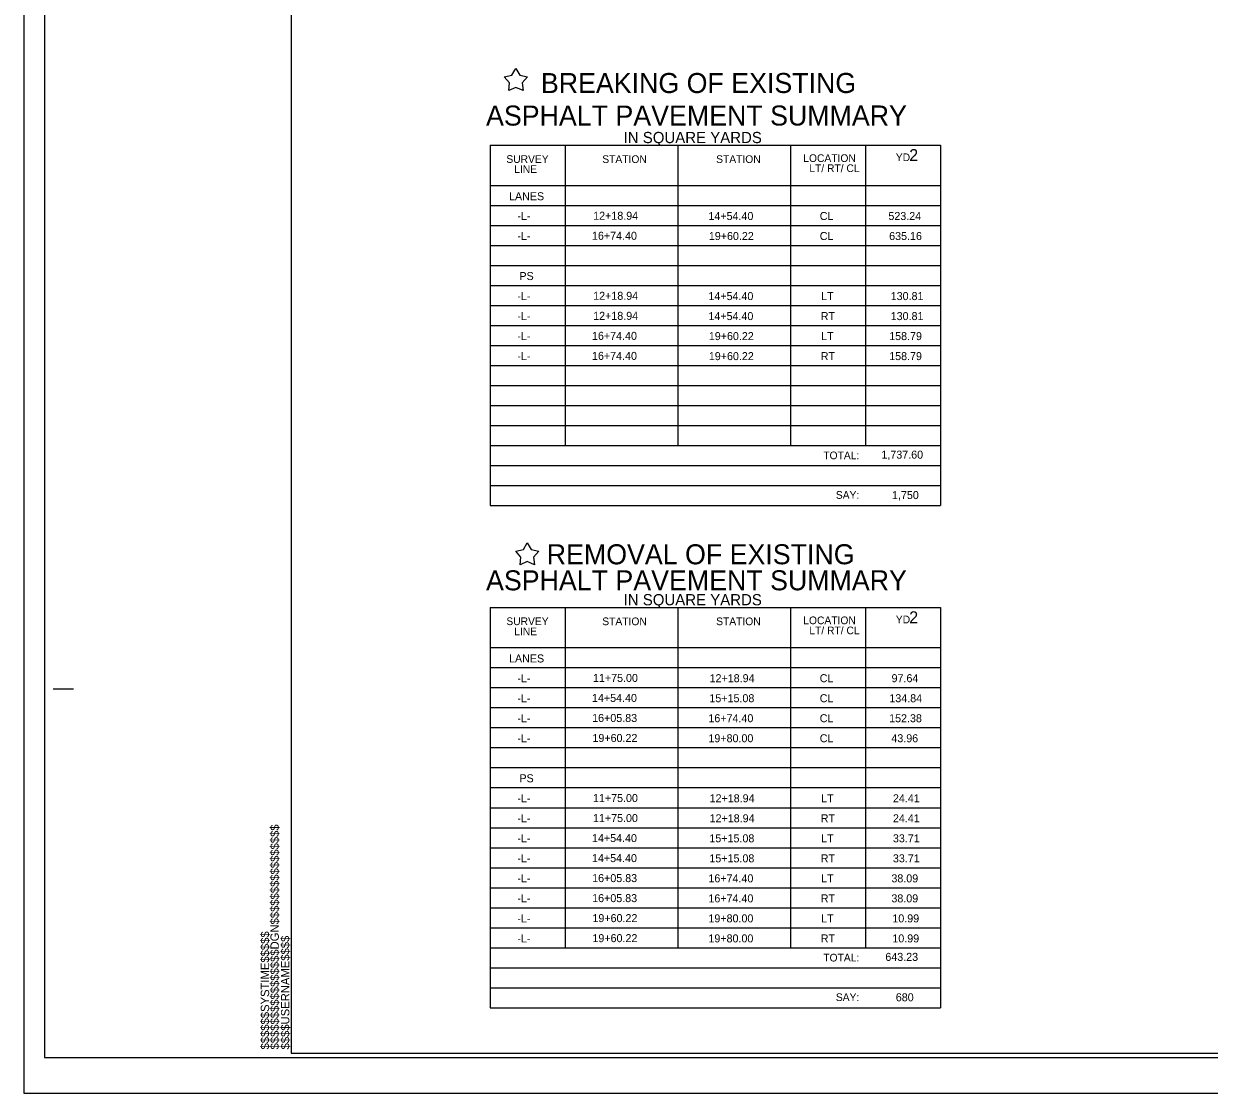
# Model space of a CAD drawing. Extents: x 9833 to 11517, y 9975 to 11331.
# Drawn here: x 9833 to 10574, y 9975 to 10643 of the extents above; entities that cross this region are included whole.
import ezdxf

# ---------------------------------------------------------------- set-up
doc = ezdxf.new("R2010")
doc.units = 0
for name, color, linetype in [('Prop Dimension Text', 7, 'Continuous'), ('Sheet Cutting Line CELL', 7, 'Continuous'), ('Sheet Pipe Summary CELL', 7, 'Continuous'), ('Sheet Plot Border Inside CELL', 7, 'Continuous'), ('Sheet Plot Border Outside CELL', 7, 'Continuous'), ('Sheet Summary CELL', 7, 'Continuous'), ('Sheet Summary Combination CELL', 7, 'Continuous'), ('Sheet Summary Combination Grid CELL', 7, 'Continuous'), ('Sheet Summary Earthwork CELL', 7, 'Continuous')]:
    doc.layers.add(name, color=color, linetype=linetype)

msp = doc.modelspace()

# ---------------------------------------------------------------- linework, layer by layer
at = {"layer": 'Sheet Cutting Line CELL'}
for p, q in [((9833, 11075), (9833, 9975)), ((9833, 9975), (11517, 9975))]:
    msp.add_line(p, q, dxfattribs=at)
at = {"layer": 'Sheet Plot Border Inside CELL'}
msp.add_lwpolyline([(11512.5, 11052.55), (9846, 11052.55), (9846, 9997.45), (11512.5, 9997.45)], close=True, dxfattribs=at)
at = {"layer": 'Sheet Plot Border Outside CELL'}
msp.add_lwpolyline([(11517, 11075), (9833, 11075), (9833, 9975), (11517, 9975)], close=True, dxfattribs=at)
at = {"layer": 'Sheet Summary CELL'}
for p, q in [((9851.5, 10227.5), (9864, 10227.5)), ((10000, 10000), (10000, 10000)), ((10000, 10000), (10000, 10000)), ((10000, 10000), (10000, 10000)), ((10000, 10000), (10000, 10000)), ((10000, 10000), (10000, 10000)), ((10000, 10000), (10000, 10000))]:
    msp.add_line(p, q, dxfattribs=at)
msp.add_lwpolyline([(11500, 11050), (10000, 11050), (10000, 10000), (11500, 10000)], close=True, dxfattribs=at)
msp.add_lwpolyline([(10137.5, 10000), (10137.5, 10000)], dxfattribs=at)
at = {"layer": 'Sheet Summary Combination CELL'}
for p, q in [((10265.57, 10566.98), (10265.57, 10566.98)), ((10271.82, 10566.88), (10271.82, 10566.88)), ((10280.87, 10567.08), (10280.87, 10567.08)), ((10286.47, 10566.98), (10286.47, 10566.98)), ((10265.57, 10278.32), (10265.57, 10278.32)), ((10271.82, 10278.22), (10271.82, 10278.22)), ((10280.87, 10278.42), (10280.87, 10278.42)), ((10286.47, 10278.32), (10286.47, 10278.32))]:
    msp.add_line(p, q, dxfattribs=at)
at = {"layer": 'Sheet Summary Combination Grid CELL'}
for p, q in [((10124.32, 10567.03), (10405.67, 10567.03)), ((10124.32, 10567.03), (10124.32, 10342.03)), ((10171.22, 10567.03), (10171.22, 10379.53)), ((10241.57, 10567.03), (10241.57, 10379.53)), ((10311.87, 10567.03), (10311.87, 10379.53)), ((10358.77, 10567.03), (10358.77, 10379.53)), ((10405.67, 10567.03), (10405.67, 10342.03)), ((10124.32, 10542.03), (10405.67, 10542.03)), ((10124.32, 10529.53), (10405.67, 10529.53)), ((10124.32, 10517.03), (10405.67, 10517.03)), ((10124.32, 10504.53), (10405.67, 10504.53)), ((10124.32, 10492.03), (10405.67, 10492.03)), ((10124.32, 10479.53), (10405.67, 10479.53)), ((10124.32, 10467.03), (10405.67, 10467.03)), ((10124.32, 10454.53), (10405.67, 10454.53)), ((10124.32, 10442.03), (10405.67, 10442.03)), ((10124.32, 10429.53), (10405.67, 10429.53)), ((10124.32, 10429.53), (10405.67, 10429.53)), ((10124.32, 10417.03), (10405.67, 10417.03)), ((10124.32, 10417.03), (10405.67, 10417.03)), ((10124.32, 10404.53), (10405.67, 10404.53)), ((10124.32, 10392.03), (10405.67, 10392.03)), ((10124.32, 10379.53), (10405.67, 10379.53)), ((10124.32, 10367.03), (10405.67, 10367.03)), ((10124.32, 10354.53), (10405.67, 10354.53)), ((10124.32, 10342.03), (10405.67, 10342.03)), ((10124.32, 10278.37), (10405.67, 10278.37)), ((10124.32, 10278.37), (10124.32, 10028.37)), ((10171.22, 10278.37), (10171.22, 10065.87)), ((10241.57, 10278.37), (10241.57, 10065.87)), ((10311.87, 10278.37), (10311.87, 10065.87)), ((10358.77, 10278.37), (10358.77, 10065.87)), ((10405.67, 10278.37), (10405.67, 10028.37)), ((10124.32, 10253.37), (10405.67, 10253.37)), ((10124.32, 10240.87), (10405.67, 10240.87)), ((10124.32, 10228.37), (10405.67, 10228.37)), ((10124.32, 10215.87), (10405.67, 10215.87)), ((10124.32, 10203.37), (10405.67, 10203.37)), ((10124.32, 10190.87), (10405.67, 10190.87)), ((10124.32, 10178.37), (10405.67, 10178.37)), ((10124.32, 10165.87), (10405.67, 10165.87)), ((10124.32, 10153.37), (10405.67, 10153.37)), ((10124.32, 10140.87), (10405.67, 10140.87)), ((10124.32, 10140.87), (10405.67, 10140.87)), ((10124.32, 10128.37), (10405.67, 10128.37)), ((10124.32, 10128.37), (10405.67, 10128.37)), ((10124.32, 10115.87), (10405.67, 10115.87)), ((10124.32, 10103.37), (10405.67, 10103.37)), ((10124.32, 10090.87), (10405.67, 10090.87)), ((10124.32, 10078.37), (10405.67, 10078.37)), ((10124.32, 10065.87), (10405.67, 10065.87)), ((10124.32, 10053.37), (10405.67, 10053.37)), ((10124.32, 10040.87), (10405.67, 10040.87)), ((10124.32, 10028.37), (10405.67, 10028.37))]:
    msp.add_line(p, q, dxfattribs=at)
at = {"layer": 'Sheet Summary Earthwork CELL'}
for points in [[(10137.96, 10610.74), (10140.42, 10614.98), (10142.87, 10610.74), (10147.66, 10609.72), (10144.38, 10606.07), (10144.9, 10601.2), (10140.42, 10603.19), (10135.94, 10601.2), (10136.45, 10606.07), (10133.17, 10609.72)], [(10145.1, 10314.56), (10147.55, 10318.81), (10150, 10314.56), (10154.8, 10313.54), (10151.52, 10309.9), (10152.03, 10305.02), (10147.55, 10307.01), (10143.07, 10305.02), (10143.58, 10309.9), (10140.3, 10313.54)]]:
    msp.add_lwpolyline(points, close=True, dxfattribs=at)

# ---------------------------------------------------------------- texts
at = {"layer": 'Prop Dimension Text'}
for s, p in [('LANES', (10136.13, 10532.72)), ('-L-', (10141.34, 10520.38)), ('12+18.94', (10188.7, 10520.54)), ('14+54.40', (10260.67, 10520.38)), ('CL', (10330.22, 10520.38)), ('523.24', (10373.09, 10520.38)), ('-L-', (10141.34, 10507.88)), ('16+74.40', (10187.96, 10508.04)), ('19+60.22', (10260.94, 10507.88)), ('CL', (10330.22, 10507.88)), ('635.16', (10373.57, 10507.88)), ('PS', (10142.62, 10482.88)), ('-L-', (10141.34, 10470.38)), ('12+18.94', (10188.7, 10470.54)), ('14+54.40', (10260.67, 10470.38)), ('LT', (10331.13, 10470.38)), ('130.81', (10374.54, 10470.38)), ('-L-', (10141.34, 10457.88)), ('12+18.94', (10188.7, 10458.04)), ('14+54.40', (10260.67, 10457.88)), ('RT', (10330.84, 10457.88)), ('130.81', (10374.54, 10457.88)), ('-L-', (10141.34, 10445.38)), ('16+74.40', (10187.96, 10445.54)), ('19+60.22', (10260.94, 10445.38)), ('LT', (10331.13, 10445.38)), ('158.79', (10373.59, 10445.38)), ('-L-', (10141.34, 10432.88)), ('16+74.40', (10187.96, 10433.04)), ('19+60.22', (10260.94, 10432.88)), ('RT', (10330.84, 10432.88)), ('158.79', (10373.59, 10432.88)), ('1,737.60', (10368.73, 10371.35)), ('1,750', (10375.35, 10346.11)), ('LANES', (10136.13, 10244.06)), ('-L-', (10141.34, 10231.73)), ('11+75.00', (10188.56, 10231.89)), ('12+18.94', (10261.41, 10231.73)), ('CL', (10330.22, 10231.72)), ('97.64', (10375.07, 10231.73)), ('-L-', (10141.34, 10219.23)), ('14+54.40', (10187.96, 10219.39)), ('15+15.08', (10261.28, 10219.23)), ('CL', (10330.22, 10219.22)), ('134.84', (10373.69, 10219.23)), ('16+05.83', (10188.07, 10206.89)), ('-L-', (10141.34, 10206.73)), ('16+74.40', (10260.67, 10206.73)), ('CL', (10330.22, 10206.72)), ('152.38', (10373.56, 10206.73)), ('-L-', (10141.34, 10194.23)), ('19+60.22', (10188.23, 10194.39)), ('19+80.00', (10260.67, 10194.23)), ('CL', (10330.22, 10194.22)), ('43.96', (10374.95, 10194.23)), ('PS', (10142.62, 10169.23)), ('-L-', (10141.34, 10156.73)), ('11+75.00', (10188.56, 10156.89)), ('12+18.94', (10261.41, 10156.73)), ('LT', (10331.13, 10156.72)), ('24.41', (10375.92, 10156.73)), ('-L-', (10141.34, 10144.23)), ('11+75.00', (10188.56, 10144.39)), ('12+18.94', (10261.41, 10144.23)), ('RT', (10330.84, 10144.22)), ('24.41', (10375.92, 10144.23)), ('-L-', (10141.34, 10131.73)), ('14+54.40', (10187.96, 10131.89)), ('15+15.08', (10261.28, 10131.73)), ('LT', (10331.13, 10131.72)), ('33.71', (10375.92, 10131.73)), ('-L-', (10141.34, 10119.23)), ('14+54.40', (10187.96, 10119.39)), ('15+15.08', (10261.28, 10119.23)), ('RT', (10330.84, 10119.22)), ('33.71', (10375.92, 10119.23)), ('-L-', (10141.34, 10106.73)), ('16+05.83', (10188.07, 10106.89)), ('16+74.40', (10260.67, 10106.73)), ('LT', (10331.13, 10106.72)), ('38.09', (10374.97, 10106.73)), ('-L-', (10141.34, 10094.23)), ('16+05.83', (10188.07, 10094.39)), ('16+74.40', (10260.67, 10094.23)), ('RT', (10330.84, 10094.22)), ('38.09', (10374.97, 10094.23)), ('-L-', (10141.34, 10081.73)), ('19+60.22', (10188.23, 10081.89)), ('19+80.00', (10260.67, 10081.73)), ('LT', (10331.13, 10081.72)), ('10.99', (10375.57, 10081.73)), ('-L-', (10141.34, 10069.23)), ('19+60.22', (10188.23, 10069.39)), ('19+80.00', (10260.67, 10069.23)), ('RT', (10330.84, 10069.22)), ('10.99', (10375.57, 10069.23)), ('643.23', (10371.2, 10057.69)), ('680', (10377.72, 10032.45))]:
    msp.add_text(s, height=5, dxfattribs=at).set_placement(p)
at = {"layer": 'Sheet Pipe Summary CELL'}
for p in [(10207.71, 10568.41), (10207.71, 10279.75)]:
    msp.add_text('IN SQUARE YARDS', height=7, dxfattribs=at).set_placement(p)
at = {"layer": 'Sheet Summary CELL'}
for s, p in [('$$$$$$$$$$$$$$$$DGN$$$$$$$$$$$$$$$$', (9992.35, 10002.36)), ('$$$$$$SYSTIME$$$$$', (9986.3, 10002.36)), ('$$$$USERNAME$$$$', (9998.93, 10002.38))]:
    msp.add_text(s, height=5.25, rotation=90, dxfattribs=at).set_placement(p)
at = {"layer": 'Sheet Summary Combination CELL'}
for s, p in [('BREAKING OF EXISTING', (10156.05, 10599.67)), ('ASPHALT PAVEMENT SUMMARY', (10121.79, 10579.35)), ('REMOVAL OF EXISTING', (10159.7, 10305.35)), ('ASPHALT PAVEMENT SUMMARY', (10121.79, 10289.09))]:
    msp.add_text(s, height=12.5001, rotation=0.01193, dxfattribs=at).set_placement(p)
for s, p in [('SURVEY', (10134.47, 10556.05)), ('STATION', (10194.38, 10555.99)), ('STATION', (10265.51, 10556.01)), ('LOCATION', (10319.93, 10556.63)), ('LINE', (10139.38, 10549.75)), ('LT/ RT/ CL', (10323.71, 10550.33)), ('TOTAL:', (10332.43, 10370.98)), ('SAY:', (10340.27, 10346.27)), ('SURVEY', (10134.47, 10267.39)), ('STATION', (10194.38, 10267.34)), ('STATION', (10265.51, 10267.35)), ('LOCATION', (10319.93, 10267.97)), ('LINE', (10139.38, 10261.09)), ('LT/ RT/ CL', (10323.71, 10261.67)), ('TOTAL:', (10332.43, 10057.32)), ('SAY:', (10340.27, 10032.61))]:
    msp.add_text(s, height=4.8, dxfattribs=at).set_placement(p)
at = {"layer": 'Sheet Summary Combination Grid CELL'}
for s, height, p in [('YD', 4.8, (10377.73, 10557.16)), ('2', 7.5, (10386.1, 10557.16)), ('YD', 4.8, (10377.73, 10268.5)), ('2', 7.5, (10386.1, 10268.5))]:
    msp.add_text(s, height=height, dxfattribs=at).set_placement(p)

doc.saveas('drawing.dxf')
